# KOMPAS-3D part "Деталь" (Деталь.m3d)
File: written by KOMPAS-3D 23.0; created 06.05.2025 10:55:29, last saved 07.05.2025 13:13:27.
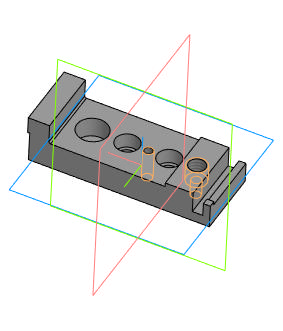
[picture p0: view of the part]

Document properties: Автор: o.malyshev; Полное имя файла: C:\Users\o.malyshev\Desktop\ступино\Деталь.m3d

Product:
- Part/product: Деталь
    Масса: 0.060886

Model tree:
1. Эскиз:1
2. Элемент выдавливания:1
     Расстояние 1 = 8
3. Эскиз:2  (with: Элемент выдавливания:1)
4. Элемент выдавливания:2
     Расстояние 1 = 6
5. Эскиз:3  (with: Элемент выдавливания:1, Элемент выдавливания:2)
6. Элемент выдавливания:3
     Расстояние 1 = 0.6
7. Эскиз:4  (with: Элемент выдавливания:1)
8. Элемент выдавливания:5
     Расстояние 2 = 20
9. Эскиз:6  (with: Элемент выдавливания:1, Элемент выдавливания:5)
10. Элемент выдавливания:8
     Расстояние 2 = 20
11. Эскиз:7  (with: Элемент выдавливания:1, Элемент выдавливания:8)
12. Элемент выдавливания:9
     Расстояние 2 = 20
13. Эскиз:8  (with: Элемент выдавливания:9)
14. Элемент выдавливания:10
     Расстояние 2 = 1
15. Эскиз:9  (with: Элемент выдавливания:1, Элемент выдавливания:10)
16. Элемент выдавливания:11
     Расстояние 1 = -28
17. Эскиз:10  (with: Элемент выдавливания:10)
18. Элемент выдавливания:12
     Расстояние 1 = 1
19. Эскиз:11  (with: Элемент выдавливания:9, Элемент выдавливания:10, Элемент выдавливания:11)
20. Элемент выдавливания:13
     Расстояние 2 = 1
21. Отверстие:1  (with: Элемент выдавливания:5)  (labels: M6)
     Глубина выреза = 5; Диаметр отверстия = 4.91747; Угол конуса дна = 118; Расстояние 1 = 10; Расстояние 2 = 4
22. M6  (with: Элемент выдавливания:5)  (labels: cil0_24705-2004 coarse)
     Длина резьбы = 5; Шаг резьбы = 1; Номинальный диаметр резьбы = 6
23. Отверстие:2  (with: Элемент выдавливания:5)  (labels: M3)
     Глубина выреза = 10; Диаметр отверстия = 2.45873; Угол конуса дна = 118; Расстояние 1 = 10; Расстояние 2 = 4
24. M3  (with: Отверстие:2, Отверстие:1, Элемент выдавливания:1)  (labels: M3; cil0_24705-2004 coarse)
     Длина резьбы = 10; Шаг резьбы = 0.5; Номинальный диаметр резьбы = 3
25. Эскиз:12  (with: Элемент выдавливания:1)
26. Элемент выдавливания:14
     Расстояние 2 = 6
27. Эскиз:13  (with: Элемент выдавливания:1)
28. Элемент выдавливания:15
     Расстояние 2 = 4.5
29. Эскиз:14  (with: Элемент выдавливания:1)
30. Элемент выдавливания:16
     Расстояние 2 = 10
31. Скругление:1  (with: Элемент выдавливания:2)
     Радиус = 0.5
32. Эскиз:15  (with: Элемент выдавливания:1)
33. Элемент выдавливания:17
     Расстояние 2 = 3
34. Отверстие:4  (with: Элемент выдавливания:1, Скругление:1, Элемент выдавливания:17, M3)  (labels: M3; cil0_24705-2004 coarse)
     Глубина выреза = 8; Диаметр отверстия = 2.45873; Угол конуса дна = 118; Расстояние 1 = -22.9; Расстояние 2 = 10; Длина резьбы = 9; Шаг резьбы = 0.5; Номинальный диаметр резьбы = 3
